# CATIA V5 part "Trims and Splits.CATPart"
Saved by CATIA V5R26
Part number: Trims and Splits
Bounding box of the stored display mesh (mm): x -163.393 to 133.26, y 0 to 550.967, z -174.504 to 157.642
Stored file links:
  D:\LinkedIn Learning\NURBS\CATIA\Class Parts\Trims and Splits.CATPart
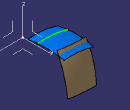
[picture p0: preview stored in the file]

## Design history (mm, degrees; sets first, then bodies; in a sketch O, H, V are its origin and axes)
AxisSystem1: origin (0, 0, 0), X (1, 0, 0), Y (0, 1, 0), Z (0, 0, 1)
Set1
  DatumSurface1
  DatumSurface2
  DatumCurve1
Body1 (main body)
